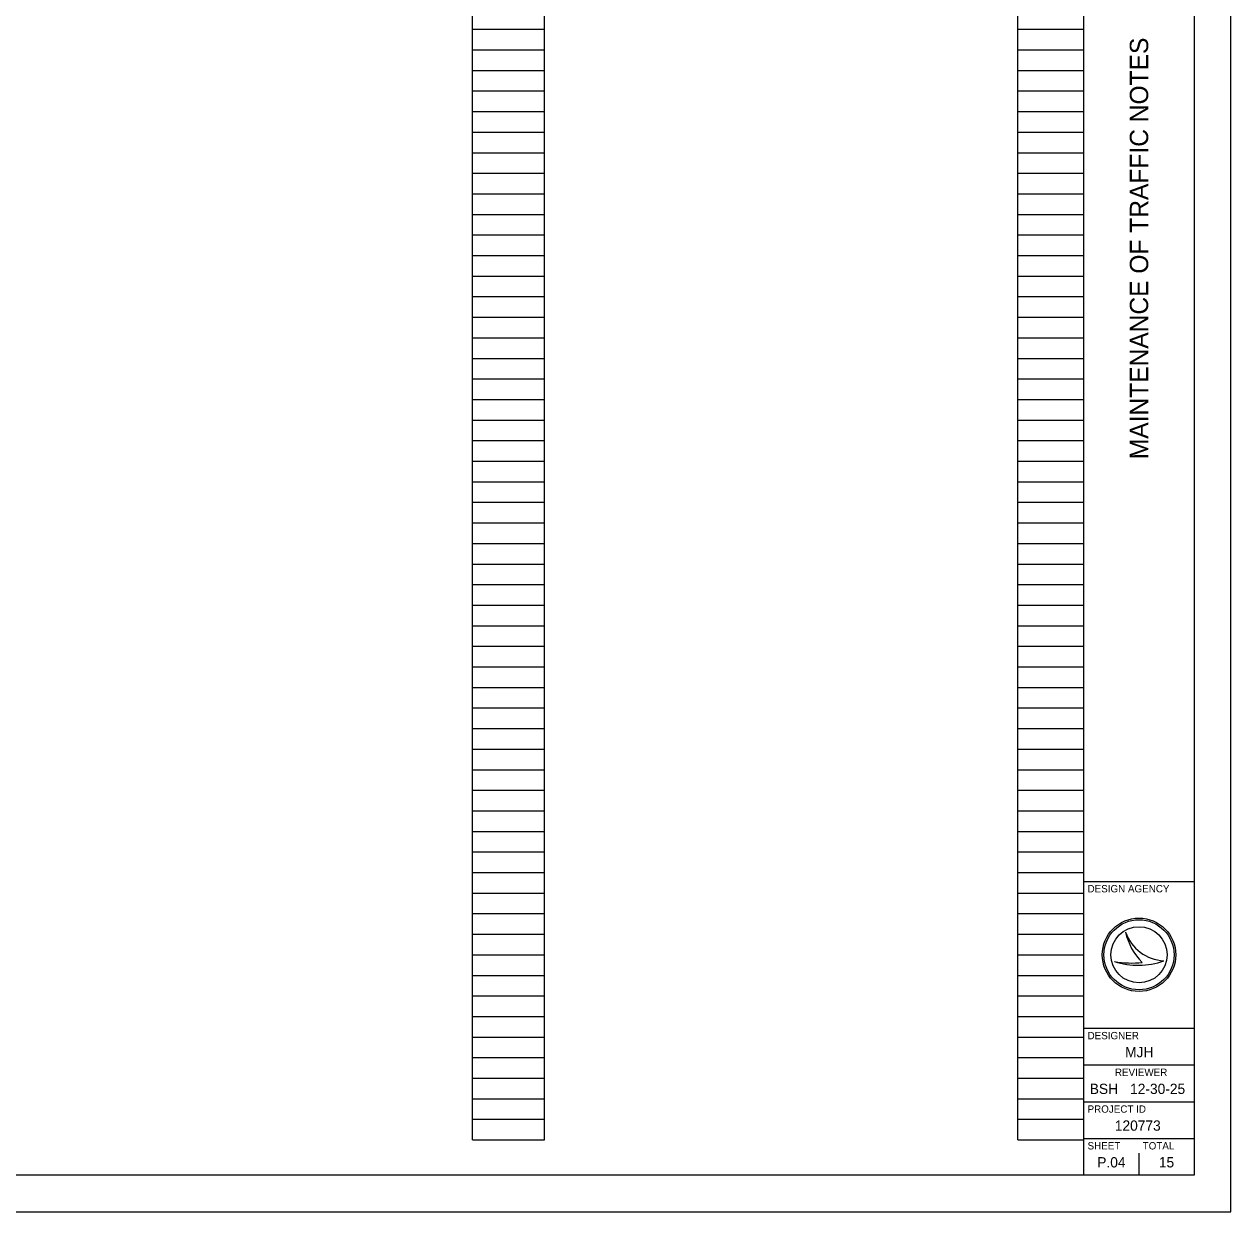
# Model space of a CAD drawing. Extents: x 0 to 34, y -4.2 to 30.9.
# Drawn here: x 17.58 to 34, y 0 to 16.17 of the extents above; entities that cross this region are included whole.
import ezdxf

# ---------------------------------------------------------------- set-up
doc = ezdxf.new("R2010")
doc.units = 0
for name, color, linetype in [('SH_Border', 7, 'Continuous'), ('SH_Cut_Line', 7, 'Continuous'), ('SH_Data', 7, 'Continuous')]:
    doc.layers.add(name, color=color, linetype=linetype)

msp = doc.modelspace()

# ---------------------------------------------------------------- linework, layer by layer
at = {"layer": 'SH_Border'}
for p, q in [((32, 0.5), (32, 21.5)), ((32, 4.5), (33.5, 4.5)), ((32, 2.5), (33.5, 2.5)), ((32, 2), (33.5, 2)), ((32, 1.5), (33.5, 1.5)), ((32, 1), (33.5, 1))]:
    msp.add_line(p, q, dxfattribs=at)
msp.add_lwpolyline([(1.5, 21.5), (33.5, 21.5), (33.5, 0.5), (1.5, 0.5)], close=True, dxfattribs=at)
at = {"layer": 'SH_Cut_Line'}
msp.add_lwpolyline([(0, 0), (34, 0), (34, 22), (0, 22)], close=True, dxfattribs=at)
at = {"layer": 'SH_Data'}
for p, q in [((23.68, 0.98), (23.68, 21.14)), ((24.66, 0.98), (24.66, 21.14)), ((31.1, 0.98), (31.1, 21.14)), ((32, 0.98), (32, 21.14)), ((23.68, 16.1), (24.66, 16.1)), ((31.1, 16.1), (32, 16.1)), ((23.68, 15.82), (24.66, 15.82)), ((31.1, 15.82), (32, 15.82)), ((23.68, 15.54), (24.66, 15.54)), ((31.1, 15.54), (32, 15.54)), ((23.68, 15.26), (24.66, 15.26)), ((31.1, 15.26), (32, 15.26)), ((23.68, 14.98), (24.66, 14.98)), ((31.1, 14.98), (32, 14.98)), ((23.68, 14.7), (24.66, 14.7)), ((31.1, 14.7), (32, 14.7)), ((23.68, 14.42), (24.66, 14.42)), ((31.1, 14.42), (32, 14.42)), ((23.68, 14.14), (24.66, 14.14)), ((31.1, 14.14), (32, 14.14)), ((23.68, 13.86), (24.66, 13.86)), ((31.1, 13.86), (32, 13.86)), ((23.68, 13.58), (24.66, 13.58)), ((31.1, 13.58), (32, 13.58)), ((23.68, 13.3), (24.66, 13.3)), ((31.1, 13.3), (32, 13.3)), ((23.68, 13.02), (24.66, 13.02)), ((31.1, 13.02), (32, 13.02)), ((23.68, 12.74), (24.66, 12.74)), ((31.1, 12.74), (32, 12.74)), ((23.68, 12.46), (24.66, 12.46)), ((31.1, 12.46), (32, 12.46)), ((23.68, 12.18), (24.66, 12.18)), ((31.1, 12.18), (32, 12.18)), ((23.68, 11.9), (24.66, 11.9)), ((31.1, 11.9), (32, 11.9)), ((23.68, 11.62), (24.66, 11.62)), ((31.1, 11.62), (32, 11.62)), ((23.68, 11.34), (24.66, 11.34)), ((31.1, 11.34), (32, 11.34)), ((23.68, 11.06), (24.66, 11.06)), ((31.1, 11.06), (32, 11.06)), ((23.68, 10.78), (24.66, 10.78)), ((31.1, 10.78), (32, 10.78)), ((23.68, 10.5), (24.66, 10.5)), ((31.1, 10.5), (32, 10.5)), ((23.68, 10.22), (24.66, 10.22)), ((31.1, 10.22), (32, 10.22)), ((23.68, 9.94), (24.66, 9.94)), ((31.1, 9.94), (32, 9.94)), ((23.68, 9.66), (24.66, 9.66)), ((31.1, 9.66), (32, 9.66)), ((23.68, 9.38), (24.66, 9.38)), ((31.1, 9.38), (32, 9.38)), ((23.68, 9.1), (24.66, 9.1)), ((31.1, 9.1), (32, 9.1)), ((23.68, 8.82), (24.66, 8.82)), ((31.1, 8.82), (32, 8.82)), ((23.68, 8.54), (24.66, 8.54)), ((31.1, 8.54), (32, 8.54)), ((23.68, 8.26), (24.66, 8.26)), ((31.1, 8.26), (32, 8.26)), ((23.68, 7.98), (24.66, 7.98)), ((31.1, 7.98), (32, 7.98)), ((23.68, 7.7), (24.66, 7.7)), ((31.1, 7.7), (32, 7.7)), ((23.68, 7.42), (24.66, 7.42)), ((31.1, 7.42), (32, 7.42)), ((23.68, 7.14), (24.66, 7.14)), ((31.1, 7.14), (32, 7.14)), ((23.68, 6.86), (24.66, 6.86)), ((31.1, 6.86), (32, 6.86)), ((23.68, 6.58), (24.66, 6.58)), ((31.1, 6.58), (32, 6.58)), ((23.68, 6.3), (24.66, 6.3)), ((31.1, 6.3), (32, 6.3)), ((23.68, 6.02), (24.66, 6.02)), ((31.1, 6.02), (32, 6.02)), ((23.68, 5.74), (24.66, 5.74)), ((31.1, 5.74), (32, 5.74)), ((23.68, 5.46), (24.66, 5.46)), ((31.1, 5.46), (32, 5.46)), ((23.68, 5.18), (24.66, 5.18)), ((31.1, 5.18), (32, 5.18)), ((23.68, 4.9), (24.66, 4.9)), ((31.1, 4.9), (32, 4.9)), ((23.68, 4.62), (24.66, 4.62)), ((31.1, 4.62), (32, 4.62)), ((23.68, 4.34), (24.66, 4.34)), ((31.1, 4.34), (32, 4.34)), ((23.68, 4.06), (24.66, 4.06)), ((31.1, 4.06), (32, 4.06)), ((23.68, 3.78), (24.66, 3.78)), ((31.1, 3.78), (32, 3.78)), ((32.567, 3.81), (32.567, 3.81)), ((23.68, 3.5), (24.66, 3.5)), ((31.1, 3.5), (32, 3.5)), ((32.75, 3.5), (32.75, 3.5)), ((32.417, 3.41), (32.417, 3.41)), ((33.087, 3.419), (33.087, 3.419)), ((23.68, 3.22), (24.66, 3.22)), ((31.1, 3.22), (32, 3.22)), ((23.68, 2.94), (24.66, 2.94)), ((31.1, 2.94), (32, 2.94)), ((23.68, 2.66), (24.66, 2.66)), ((31.1, 2.66), (32, 2.66)), ((23.68, 2.38), (24.66, 2.38)), ((31.1, 2.38), (32, 2.38)), ((23.68, 2.1), (24.66, 2.1)), ((31.1, 2.1), (32, 2.1)), ((23.68, 1.82), (24.66, 1.82)), ((31.1, 1.82), (32, 1.82)), ((23.68, 1.54), (24.66, 1.54)), ((31.1, 1.54), (32, 1.54)), ((23.68, 1.26), (24.66, 1.26)), ((31.1, 1.26), (32, 1.26)), ((23.68, 0.98), (24.66, 0.98)), ((31.1, 0.98), (32, 0.98)), ((32.375, 0.675), (32.375, 0.675)), ((32.75, 0.5), (32.75, 0.8))]:
    msp.add_line(p, q, dxfattribs=at)
for radius in [0.5, 0.477, 0.477, 0.382]:
    msp.add_circle((32.75, 3.5), radius, dxfattribs=at)
for centre, radius, start, end in [((33.116, 3.998), 0.58, 198.9257, 198.9319), ((33.347, 3.97), 0.796, 191.6379, 191.6421), ((33.116, 3.998), 0.58, 198.9319, 267.1657), ((33.347, 3.97), 0.796, 191.6421, 226.0947), ((32.739, 4.37), 1.013, 251.4576, 290.0832), ((32.648, 4.654), 1.266, 259.4964, 259.4995), ((32.739, 4.37), 1.013, 251.4527, 251.4576), ((32.648, 4.654), 1.266, 259.4995, 276.6672)]:
    msp.add_arc(centre, radius, start, end, dxfattribs=at)

# ---------------------------------------------------------------- texts
msp.add_text('MAINTENANCE OF TRAFFIC NOTES', height=0.25, rotation=90, dxfattribs=at).set_placement((32.875, 10.247))
for s, height, p in [('DESIGN AGENCY', 0.1, (32.05, 4.35)), ('DESIGNER', 0.1, (32.05, 2.35)), ('MJH', 0.14, (32.561, 2.105)), ('REVIEWER', 0.1, (32.422, 1.85)), ('BSH', 0.14, (32.08, 1.605)), ('12-30-25', 0.14, (32.629, 1.605)), ('PROJECT ID', 0.1, (32.05, 1.35)), ('120773', 0.14, (32.421, 1.105)), ('SHEET', 0.1, (32.05, 0.85)), ('TOTAL', 0.1, (32.8, 0.85)), ('P.04', 0.14, (32.182, 0.605)), ('15', 0.14, (33.02, 0.605))]:
    msp.add_text(s, height=height, dxfattribs=at).set_placement(p)

doc.saveas('drawing.dxf')
